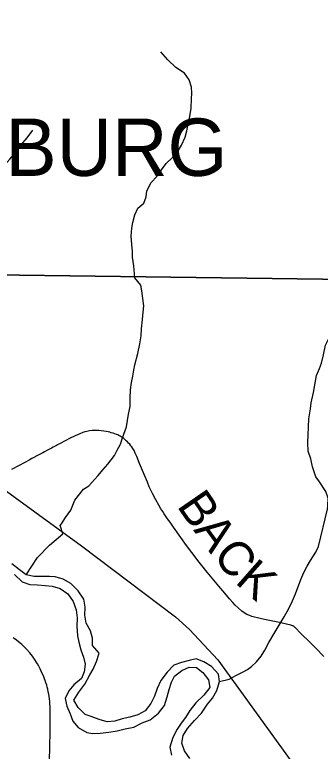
# Model space of a CAD drawing. Extents: x 0 to 34, y 0 to 22.
# Drawn here: x 6.225 to 6.729, y 15.855 to 17.07 of the extents above; entities that cross this region are included whole.
import ezdxf

# ---------------------------------------------------------------- set-up
doc = ezdxf.new("R2010")
doc.units = 0
for name, color, linetype in [('GM_X_Corporation_Text', 7, 'Continuous'), ('GM_X_Major_River', 7, 'Continuous'), ('GM_X_Minor_River', 7, 'Continuous'), ('GM_X_Rail_Line', 7, 'Continuous'), ('GM_X_State_Route', 7, 'Continuous'), ('GM_X_Township_Road', 7, 'Continuous'), ('GM_X_Township_Road_Text', 7, 'Continuous'), ('SH_Cut_Line', 7, 'Continuous')]:
    doc.layers.add(name, color=color, linetype=linetype)

msp = doc.modelspace()

# ---------------------------------------------------------------- linework, layer by layer
at = {"layer": 'GM_X_Major_River'}
for points in [[(6.5138, 15.8428), (6.5049, 15.8552), (6.5006, 15.868), (6.503, 15.881), (6.5101, 15.8924), (6.5213, 15.9055), (6.5332, 15.9178), (6.5429, 15.9323), (6.5511, 15.9423), (6.5581, 15.9549), (6.5629, 15.9698), (6.5612, 15.9822), (6.5496, 15.9946), (6.5366, 16.0024), (6.5244, 16.0072), (6.5124, 16.0043), (6.5003, 16.0011), (6.4874, 15.9968), (6.4766, 15.9853), (6.4662, 15.9715), (6.4599, 15.9585), (6.4555, 15.9459), (6.4496, 15.9337), (6.4399, 15.9214), (6.4279, 15.9148), (6.4147, 15.9112), (6.4022, 15.908), (6.3901, 15.9045), (6.3772, 15.9035), (6.3643, 15.9072), (6.351, 15.9119), (6.3414, 15.9156), (6.3299, 15.9268), (6.3225, 15.9392), (6.3307, 15.9522), (6.3408, 15.9656), (6.3489, 15.9809), (6.3544, 15.9905), (6.36, 16.003), (6.364, 16.0164), (6.3532, 16.0291), (6.3534, 16.0416), (6.3502, 16.0534), (6.3428, 16.0661), (6.3407, 16.0794), (6.3413, 16.0923), (6.3389, 16.1055), (6.3299, 16.1194), (6.3176, 16.1318), (6.3047, 16.1388), (6.2917, 16.1428), (6.2822, 16.1431), (6.2686, 16.1433), (6.2568, 16.1431), (6.2439, 16.146), (6.2328, 16.1542), (6.2205, 16.1639)], [(6.2246, 16.1465), (6.2372, 16.1345), (6.2502, 16.1301), (6.2627, 16.1295), (6.2752, 16.1282), (6.287, 16.1272), (6.2999, 16.1232), (6.3126, 16.1143), (6.3215, 16.1019), (6.3262, 16.0883), (6.3279, 16.0747), (6.3277, 16.061), (6.3287, 16.0451), (6.3307, 16.0349), (6.3343, 16.022), (6.3386, 16.01), (6.3414, 15.9986), (6.3397, 15.9861), (6.3349, 15.9746), (6.3226, 15.9642), (6.3144, 15.9546), (6.3081, 15.942), (6.3109, 15.9292), (6.3164, 15.9164), (6.3207, 15.9043), (6.3296, 15.8942), (6.3437, 15.8856), (6.3536, 15.8843), (6.3661, 15.8844), (6.3801, 15.8861), (6.3937, 15.8886), (6.407, 15.8918), (6.4213, 15.8946), (6.4349, 15.9017), (6.4481, 15.9068), (6.462, 15.9176), (6.472, 15.9302), (6.4764, 15.9443), (6.4796, 15.9569), (6.4833, 15.9687), (6.4884, 15.9786), (6.5004, 15.9879), (6.5125, 15.9933), (6.5246, 15.9931), (6.5354, 15.9849), (6.5446, 15.9725), (6.5467, 15.9601), (6.537, 15.9474), (6.5239, 15.9347), (6.5139, 15.9221), (6.5064, 15.9106), (6.4997, 15.901), (6.493, 15.8914), (6.4856, 15.8777), (6.4806, 15.8617), (6.4834, 15.8485)]]:
    msp.add_lwpolyline(points, dxfattribs=at)
at = {"layer": 'GM_X_Minor_River'}
for points in [[(6.423, 16.636), (6.4214, 16.656), (6.4194, 16.67), (6.419, 16.6795), (6.4181, 16.6913), (6.4173, 16.7046), (6.4183, 16.7178), (6.4198, 16.7273), (6.4231, 16.7399), (6.428, 16.7509), (6.4378, 16.7593), (6.4415, 16.7699), (6.443, 16.7798), (6.4501, 16.7935), (6.4591, 16.8034), (6.467, 16.8145), (6.4746, 16.8248), (6.4859, 16.8355), (6.4946, 16.8458), (6.5002, 16.8553), (6.5062, 16.8682), (6.5088, 16.8789), (6.5117, 16.8925), (6.5136, 16.9024), (6.5157, 16.9161), (6.5164, 16.9316), (6.5171, 16.9411), (6.5163, 16.951), (6.5128, 16.9631), (6.5047, 16.9737), (6.4906, 16.9834), (6.4776, 16.9959), (6.4661, 17.0091)], [(6.0744, 16.6398), (6.085, 16.6516), (6.0963, 16.6645), (6.1004, 16.6782), (6.1056, 16.6889), (6.1143, 16.7014), (6.1195, 16.7113), (6.1286, 16.7216), (6.135, 16.7315), (6.1463, 16.7456), (6.1602, 16.759), (6.1662, 16.7719), (6.1745, 16.7819), (6.1847, 16.7941), (6.1975, 16.8089), (6.208, 16.8219), (6.2171, 16.8318), (6.2254, 16.8417), (6.2352, 16.8551), (6.2457, 16.8669), (6.2547, 16.8799)], [(6.3002, 16.2271), (6.3024, 16.23), (6.3088, 16.2404), (6.3177, 16.2527), (6.3239, 16.2694), (6.3385, 16.2875), (6.3471, 16.293), (6.3621, 16.3095), (6.3711, 16.3195), (6.3786, 16.3284), (6.3894, 16.3426), (6.3942, 16.3514), (6.3994, 16.3617), (6.4026, 16.372), (6.4092, 16.3903), (6.4127, 16.4109), (6.4152, 16.4238), (6.4154, 16.4375), (6.4159, 16.4512), (6.4176, 16.4634), (6.4198, 16.474), (6.4215, 16.4835), (6.4229, 16.4923), (6.428, 16.511), (6.4312, 16.5273), (6.4336, 16.5403), (6.4342, 16.5521), (6.4355, 16.5673), (6.4369, 16.5794), (6.4378, 16.5897), (6.4365, 16.6022), (6.4344, 16.6147), (6.4332, 16.6238), (6.423, 16.636)], [(6.7408, 16.2545), (6.7412, 16.2598), (6.7417, 16.2727), (6.7382, 16.2833), (6.7277, 16.2995), (6.7215, 16.3077), (6.7163, 16.324), (6.7134, 16.3376), (6.7091, 16.3501), (6.7085, 16.3641), (6.709, 16.377), (6.7102, 16.4032), (6.7126, 16.42), (6.714, 16.4299), (6.7179, 16.447), (6.7224, 16.4748), (6.7276, 16.4863), (6.7309, 16.495), (6.7341, 16.5091), (6.7373, 16.5251), (6.7454, 16.5404), (6.7528, 16.5584), (6.7621, 16.5699)], [(6.5629, 15.9698), (6.5789, 15.9735), (6.5905, 15.9802), (6.6015, 15.9857), (6.6086, 15.9896), (6.6157, 15.9946), (6.6239, 16.0024), (6.6314, 16.0116), (6.6373, 16.0216), (6.6443, 16.0342), (6.6527, 16.0492), (6.6609, 16.0626), (6.6694, 16.0764), (6.6771, 16.0902), (6.6833, 16.1032), (6.6881, 16.1147), (6.6968, 16.1384), (6.7019, 16.1498), (6.7074, 16.1602), (6.7129, 16.1694), (6.7218, 16.1832), (6.7262, 16.1928), (6.7408, 16.2545)], [(6.2439, 16.146), (6.2627, 16.1744), (6.2824, 16.195), (6.3043, 16.2137), (6.3002, 16.2271)]]:
    msp.add_lwpolyline(points, dxfattribs=at)
at = {"layer": 'GM_X_Rail_Line'}
for points in [[(4.5408, 18.3763), (4.5402, 18.2851), (4.5419, 17.9684), (4.5429, 17.9404), (4.5474, 17.7028), (4.5489, 17.6578), (4.8158, 17.6467), (4.9624, 17.6496), (4.9797, 17.6498), (5.2052, 17.638), (5.3403, 17.635), (5.6743, 17.6274), (5.6656, 16.9939), (5.6628, 16.7899), (5.6628, 16.7878), (5.6614, 16.7344), (5.6594, 16.6485), (5.9824, 16.6436), (7.149, 16.6283)], [(7.149, 16.6283), (5.9824, 16.6436), (5.6594, 16.6485), (5.6614, 16.7344), (5.6628, 16.7878), (5.6628, 16.7899), (5.6656, 16.9939), (5.6743, 17.6274), (5.3403, 17.635), (5.2052, 17.638), (4.9797, 17.6498), (4.9624, 17.6496), (4.8158, 17.6467), (4.5489, 17.6578), (4.5478, 16.582), (4.5509, 15.5331), (4.5658, 14.9668), (4.5781, 14.1), (8.76, 14.1)], [(5.3095, 16.5985), (5.3508, 16.594), (5.3973, 16.594), (5.6925, 16.6066), (5.736, 16.6059), (5.7722, 16.5963), (5.8064, 16.5796), (5.8475, 16.5514), (6.0386, 16.4095), (6.3353, 16.1939), (6.4903, 16.0765), (6.5132, 16.0558), (6.5602, 16.0058), (6.7796, 15.7014)]]:
    msp.add_lwpolyline(points, dxfattribs=at)
at = {"layer": 'GM_X_State_Route'}
msp.add_lwpolyline([(6.2824, 15.8375), (6.2828, 15.8635), (6.2832, 15.8859), (6.2834, 15.8958), (6.2834, 15.9017), (6.2834, 15.9132), (6.2834, 15.9182), (6.2833, 15.9238), (6.2832, 15.9282), (6.283, 15.933), (6.2827, 15.9369), (6.2823, 15.941), (6.2818, 15.9453), (6.2811, 15.949), (6.2803, 15.953), (6.2795, 15.957), (6.2786, 15.9603), (6.2777, 15.9638), (6.2765, 15.9676), (6.2752, 15.9715), (6.274, 15.9745), (6.2722, 15.979), (6.2705, 15.9829), (6.2687, 15.9872), (6.267, 15.9907), (6.2646, 15.9951), (6.2625, 15.9988), (6.2603, 16.0024), (6.2585, 16.0052), (6.2563, 16.0086), (6.2541, 16.0117), (6.2497, 16.0173), (6.2452, 16.0225), (6.2423, 16.0255), (6.2398, 16.0279), (6.2368, 16.0307), (6.2338, 16.0332), (6.228, 16.0379), (6.2223, 16.0419)], dxfattribs=at)
at = {"layer": 'GM_X_Township_Road'}
msp.add_lwpolyline([(6.735, 16.011), (6.7215, 16.0248), (6.7123, 16.034), (6.6969, 16.0493), (6.6876, 16.0588), (6.6866, 16.0596), (6.6856, 16.0605), (6.6847, 16.0611), (6.6839, 16.0615), (6.6831, 16.0619), (6.6822, 16.0621), (6.6812, 16.0624), (6.6802, 16.0626), (6.6732, 16.0643), (6.6618, 16.0671), (6.6533, 16.069), (6.6454, 16.0706), (6.6369, 16.0723), (6.6296, 16.0739), (6.6254, 16.0748), (6.6205, 16.076), (6.6158, 16.0774), (6.6111, 16.0791), (6.6077, 16.0807), (6.6034, 16.0831), (6.5994, 16.086), (6.5933, 16.0913), (6.5885, 16.0961), (6.5847, 16.1002), (6.5793, 16.1063), (6.5713, 16.1157), (6.5617, 16.1272), (6.5423, 16.1505), (6.5291, 16.167), (6.5169, 16.1827), (6.5084, 16.1942), (6.499, 16.2073), (6.4868, 16.2245), (6.4811, 16.2326), (6.4771, 16.2386), (6.475, 16.2417), (6.4715, 16.2468), (6.4691, 16.2504), (6.4661, 16.2551), (6.4626, 16.261), (6.4577, 16.2696), (6.4527, 16.2789), (6.4505, 16.2834), (6.4469, 16.2913), (6.4438, 16.2987), (6.4405, 16.3067), (6.431, 16.3297), (6.4261, 16.3411), (6.4236, 16.3469), (6.4217, 16.3509), (6.4199, 16.3542), (6.418, 16.357), (6.4165, 16.359), (6.4146, 16.3615), (6.4129, 16.3634), (6.4111, 16.3653), (6.409, 16.3673), (6.4067, 16.3692), (6.4047, 16.3709), (6.4027, 16.3724), (6.4006, 16.3737), (6.3989, 16.3748), (6.3968, 16.3759), (6.3949, 16.3768), (6.3927, 16.3777), (6.3903, 16.3786), (6.3876, 16.3795), (6.3839, 16.3805), (6.3816, 16.3811), (6.3792, 16.3817), (6.3757, 16.3824), (6.3718, 16.3829), (6.3678, 16.3835), (6.3638, 16.3839), (6.3607, 16.3842), (6.3573, 16.3843), (6.3527, 16.3841), (6.3483, 16.3836), (6.3441, 16.3827), (6.3407, 16.3817), (6.3371, 16.3806), (6.3325, 16.3788), (6.3245, 16.3754), (6.3167, 16.3716), (6.3002, 16.3629), (6.2953, 16.3603), (6.2937, 16.3595), (6.2905, 16.3578), (6.2884, 16.3567), (6.2857, 16.3552), (6.2832, 16.3538), (6.2779, 16.3509), (6.2741, 16.3489), (6.2714, 16.3475), (6.2703, 16.3469), (6.2649, 16.344), (6.2534, 16.338), (6.2486, 16.3353), (6.2324, 16.3264), (6.2198, 16.3197)], dxfattribs=at)
at = {"layer": 'SH_Cut_Line'}
for points in [[(2.1, 14.1), (4.5781, 14.1), (4.5658, 14.9668), (4.5509, 15.5331), (4.5478, 16.582), (4.5489, 17.6578), (4.8158, 17.6467), (4.9624, 17.6496), (4.9797, 17.6498), (5.2052, 17.638), (5.3403, 17.635), (5.6743, 17.6274), (5.6656, 16.9939), (5.6628, 16.7899), (5.6628, 16.7878), (5.6614, 16.7344), (5.6594, 16.6485), (5.9824, 16.6436), (7.149, 16.6283)], [(7.149, 16.6283), (5.9824, 16.6436), (5.6594, 16.6485), (5.6614, 16.7344), (5.6628, 16.7878), (5.6628, 16.7899), (5.6656, 16.9939), (5.6743, 17.6274), (5.3403, 17.635), (5.2052, 17.638), (4.9797, 17.6498), (4.9624, 17.6496), (4.8158, 17.6467), (4.5489, 17.6578), (4.5478, 16.582), (4.5509, 15.5331), (4.5658, 14.9668), (4.5781, 14.1), (8.9, 14.1)]]:
    msp.add_lwpolyline(points, dxfattribs=at)

# ---------------------------------------------------------------- texts
at = {"layer": 'GM_X_Corporation_Text'}
msp.add_text('MACKSBURG', height=0.0947, rotation=0, dxfattribs=at).set_placement((5.7593, 16.8043))
at = {"layer": 'GM_X_Township_Road_Text'}
for s, rotation, p in [('B', 304.5377, (6.4913, 16.2598)), ('A', 306.3158, (6.5189, 16.2198)), ('C', 308.7513, (6.5501, 16.1774)), ('K', 318.6656, (6.5867, 16.1333))]:
    msp.add_text(s, height=0.0568, rotation=rotation, dxfattribs=at).set_placement(p)

doc.saveas('drawing.dxf')
